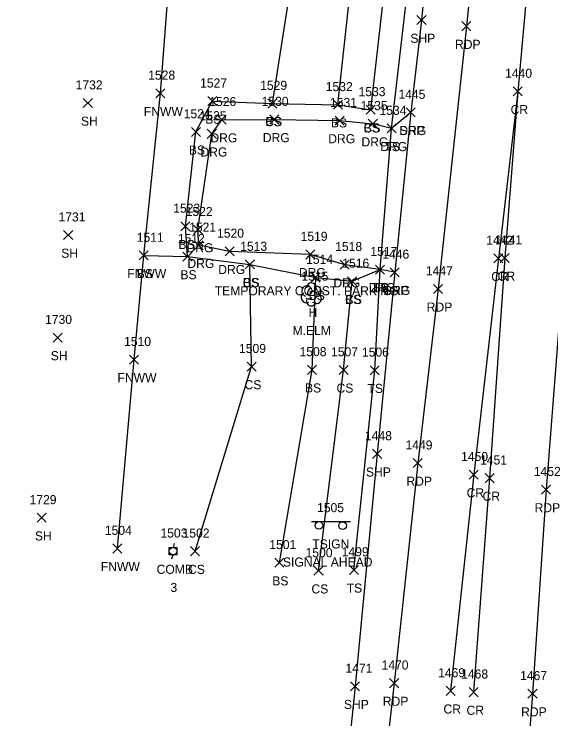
# Model space of a CAD drawing. Extents: x 1443960 to 1446865, y 610387 to 616706.
# Drawn here: x 1446473.8 to 1446592.3, y 610855.3 to 611010.8 of the extents above; entities that cross this region are included whole.
import ezdxf

# ---------------------------------------------------------------- set-up
doc = ezdxf.new("R2010")
doc.units = 0
for name, color, linetype in [('L_A', 7, 'Continuous'), ('L_C', 7, 'Continuous'), ('L_I', 7, 'Continuous'), ('L_TIC', 7, 'Continuous'), ('LELB', 7, 'Continuous'), ('LFNC', 7, 'Continuous'), ('LTD', 7, 'Continuous'), ('P_A', 7, 'Continuous'), ('P_I', 7, 'Continuous'), ('P_TIC', 7, 'Continuous'), ('PET', 7, 'Continuous'), ('PRC', 7, 'Continuous'), ('PSP', 7, 'Continuous'), ('R_A', 7, 'Continuous'), ('R_C', 7, 'Continuous'), ('R_I', 7, 'Continuous'), ('R_TIC', 7, 'Continuous'), ('RDG', 7, 'Continuous'), ('S_A', 7, 'Continuous'), ('S_C', 7, 'Continuous'), ('S_I', 7, 'Continuous'), ('SSGN', 7, 'Continuous'), ('U_A', 7, 'Continuous'), ('U_C', 7, 'Continuous'), ('U_I', 7, 'Continuous'), ('UP', 7, 'Continuous')]:
    doc.layers.add(name, color=color, linetype=linetype)

msp = doc.modelspace()

# ---------------------------------------------------------------- linework, layer by layer
at = {"layer": 'L_TIC'}
for points in [[(1446505.14, 610992.3), (1446507.14, 610994.3)], [(1446507.14, 610992.3), (1446505.14, 610994.3)], [(1446489.12, 610990.15), (1446491.12, 610992.15)], [(1446491.12, 610990.15), (1446489.12, 610992.15)], [(1446516.6, 610990.57), (1446518.6, 610992.57)], [(1446518.6, 610990.57), (1446516.6, 610992.57)], [(1446529.86, 610990.05), (1446531.86, 610992.05)], [(1446531.86, 610990.05), (1446529.86, 610992.05)], [(1446529.86, 610990.05), (1446531.86, 610992.05)], [(1446531.86, 610990.05), (1446529.86, 610992.05)], [(1446544.33, 610989.77), (1446546.33, 610991.77)], [(1446546.33, 610989.77), (1446544.33, 610991.77)], [(1446544.33, 610989.77), (1446546.33, 610991.77)], [(1446546.33, 610989.77), (1446544.33, 610991.77)], [(1446551.56, 610988.66), (1446553.56, 610990.66)], [(1446553.56, 610988.66), (1446551.56, 610990.66)], [(1446551.56, 610988.66), (1446553.56, 610990.66)], [(1446553.56, 610988.66), (1446551.56, 610990.66)], [(1446512.98, 610983.78), (1446514.98, 610985.78)], [(1446514.98, 610983.78), (1446512.98, 610985.78)], [(1446556.18, 610984.54), (1446558.18, 610986.54)], [(1446558.18, 610984.54), (1446556.18, 610986.54)], [(1446510.67, 610962.96), (1446512.67, 610964.96)], [(1446512.67, 610962.96), (1446510.67, 610964.96)], [(1446484.78, 610961.03), (1446486.78, 610963.03)], [(1446486.78, 610961.03), (1446484.78, 610963.03)], [(1446501.47, 610956.54), (1446503.47, 610958.54)], [(1446503.47, 610956.54), (1446501.47, 610958.54)], [(1446501.47, 610956.54), (1446503.47, 610958.54)], [(1446503.47, 610956.54), (1446501.47, 610958.54)], [(1446511.12, 610956.29), (1446513.12, 610958.29)], [(1446513.12, 610956.29), (1446511.12, 610958.29)], [(1446511.12, 610956.29), (1446513.12, 610958.29)], [(1446513.12, 610956.29), (1446511.12, 610958.29)], [(1446524.88, 610954.55), (1446526.88, 610956.55)], [(1446526.88, 610954.55), (1446524.88, 610956.55)], [(1446524.88, 610954.55), (1446526.88, 610956.55)], [(1446526.88, 610954.55), (1446524.88, 610956.55)], [(1446553.61, 610953.43), (1446555.61, 610955.43)], [(1446555.61, 610953.43), (1446553.61, 610955.43)], [(1446553.61, 610953.43), (1446555.61, 610955.43)], [(1446555.61, 610953.43), (1446553.61, 610955.43)], [(1446539.42, 610951.68), (1446541.42, 610953.68)], [(1446541.42, 610951.68), (1446539.42, 610953.68)], [(1446539.42, 610951.68), (1446541.42, 610953.68)], [(1446541.42, 610951.68), (1446539.42, 610953.68)], [(1446547.46, 610950.84), (1446549.46, 610952.84)], [(1446549.46, 610950.84), (1446547.46, 610952.84)], [(1446547.46, 610950.84), (1446549.46, 610952.84)], [(1446549.46, 610950.84), (1446547.46, 610952.84)], [(1446482.46, 610938.43), (1446484.46, 610940.43)], [(1446484.46, 610938.43), (1446482.46, 610940.43)], [(1446499.33, 610933.58), (1446501.33, 610935.58)], [(1446501.33, 610933.58), (1446499.33, 610935.58)], [(1446525.27, 610932.03), (1446527.27, 610934.03)], [(1446527.27, 610932.03), (1446525.27, 610934.03)], [(1446538.62, 610931.32), (1446540.62, 610933.32)], [(1446540.62, 610931.32), (1446538.62, 610933.32)], [(1446545.57, 610931.29), (1446547.57, 610933.29)], [(1446547.57, 610931.29), (1446545.57, 610933.29)], [(1446552.44, 610931.22), (1446554.44, 610933.22)], [(1446554.44, 610931.22), (1446552.44, 610933.22)], [(1446478.96, 610898.69), (1446480.96, 610900.69)], [(1446480.96, 610898.69), (1446478.96, 610900.69)], [(1446495.64, 610891.92), (1446497.64, 610893.92)], [(1446497.64, 610891.92), (1446495.64, 610893.92)], [(1446512.8, 610891.32), (1446514.8, 610893.32)], [(1446514.8, 610891.32), (1446512.8, 610893.32)], [(1446531.39, 610888.78), (1446533.39, 610890.78)], [(1446533.39, 610888.78), (1446531.39, 610890.78)], [(1446547.85, 610887.19), (1446549.85, 610889.19)], [(1446549.85, 610887.19), (1446547.85, 610889.19)], [(1446540.03, 610887), (1446542.03, 610889)], [(1446542.03, 610887), (1446540.03, 610889)]]:
    msp.add_lwpolyline(points, dxfattribs=at)
at = {"layer": 'LELB'}
for points in [[(1446548.85, 610888.19), (1446553.44, 610932.22), (1446554.61, 610954.43), (1446557.18, 610985.54), (1446561.83, 611026.07), (1446565.58, 611053.66), (1446570.69, 611096.92), (1446573.29, 611130.79), (1446568.51, 611145), (1446569.91, 611148.66), (1446564.88, 611156.7), (1446536.84, 611169.59), (1446508.69, 611183.48), (1446466.55, 611207.56), (1446427.27, 611227.8), (1446388.8, 611245), (1446349.69, 611268.25), (1446343.09, 611268.96)], [(1446545.33, 610990.77), (1446549.45, 611028.52), (1446549.03, 611055.59), (1446553.29, 611104.25), (1446542.01, 611115.66), (1446540.05, 611127.24), (1446544.04, 611129.96), (1446551.51, 611136.49), (1446553.27, 611138.91), (1446550.53, 611149.51), (1446533.12, 611159.93), (1446498.33, 611176.52), (1446468.4, 611193.46), (1446432.91, 611211.11), (1446396.49, 611230.29), (1446366.67, 611244.64), (1446348.43, 611256.48)], [(1446530.86, 610991.05), (1446536.61, 611027.8), (1446530.46, 611055.9), (1446528.01, 611097.29), (1446529.9, 611126.45), (1446531.13, 611139.44), (1446489.18, 611159.91), (1446465.02, 611182.42), (1446422.58, 611193.97), (1446390.63, 611222.09), (1446361.12, 611230.87), (1446345.74, 611242.49)], [(1446552.56, 610989.66), (1446556.82, 611027.38), (1446558.99, 611054.38), (1446562.05, 611102.47), (1446562.29, 611110), (1446552.62, 611117.46), (1446544.98, 611124.73), (1446545.64, 611126.22), (1446556.66, 611130.04), (1446565.54, 611129.7), (1446560.88, 611143.04), (1446563.36, 611147.94)], [(1446512.12, 610957.29), (1446511.67, 610963.96), (1446513.98, 610984.78), (1446517.6, 610991.57), (1446530.86, 610991.05), (1446545.33, 610990.77), (1446552.56, 610989.66)], [(1446502.47, 610957.54), (1446512.12, 610957.29), (1446525.88, 610955.55), (1446540.42, 610952.68), (1446548.46, 610951.84), (1446554.61, 610954.43)], [(1446513.8, 610892.32), (1446526.27, 610933.03), (1446525.88, 610955.55)], [(1446532.39, 610889.78), (1446539.62, 610932.32), (1446540.42, 610952.68)], [(1446541.03, 610888), (1446546.57, 610932.29), (1446548.46, 610951.84)]]:
    msp.add_lwpolyline(points, dxfattribs=at)
at = {"layer": 'LFNC'}
msp.add_lwpolyline([(1446496.64, 610892.92), (1446500.33, 610934.58), (1446502.47, 610957.54), (1446506.14, 610993.3), (1446509.27, 611033.76), (1446510.72, 611057.66), (1446494.01, 611076.45)], dxfattribs=at)
at = {"layer": 'LTD'}
msp.add_line((1446539.4, 610948.98), (1446539.4, 610948.98), dxfattribs=at)
msp.add_line((1446539.4, 610948.98), (1446539.4, 610948.98), dxfattribs=at)
msp.add_arc((1446539.45, 610950.42), 1.05, 335.5272, 180.9563, dxfattribs=at)
for centre, major_axis, ratio, start_param, end_param in [((1446538.61, 610949.65), (1.21, -0.51), 0.895232, 1.570796, 4.712389), ((1446539.19, 610949.44), (-0.208, -0.792), 0.645439, 3.141593, 6.283185), ((1446539.9, 610948.82), (-0.5, 0.667), 0.989748, 3.141593, 6.283185), ((1446540.44, 610949.57), (-1.14, -0.48), 0.949671, 1.570796, 4.712389), ((1446538.32, 610948.27), (0.58, -1.04), 0.959034, 3.141593, 6.283185), ((1446538.94, 610948.23), (-0.625, -0.083), 0.423636, 0, 3.141593), ((1446540.4, 610948.15), (-1.09, 0.79), 0.841452, 1.570796, 4.712389), ((1446539.4, 610947.48), (0.26, 1.06), 0.942809, 1.570796, 4.712389)]:
    msp.add_ellipse(centre, major_axis=major_axis, ratio=ratio, start_param=start_param, end_param=end_param, dxfattribs=at)
at = {"layer": 'P_TIC'}
for points in [[(1446562.76, 611008.43), (1446564.76, 611010.43)], [(1446564.76, 611008.43), (1446562.76, 611010.43)], [(1446572.67, 611007.09), (1446574.67, 611009.09)], [(1446574.67, 611007.09), (1446572.67, 611009.09)], [(1446584, 610992.71), (1446586, 610994.71)], [(1446586, 610992.71), (1446584, 610994.71)], [(1446584, 610992.71), (1446586, 610994.71)], [(1446586, 610992.71), (1446584, 610994.71)], [(1446560.38, 610988.08), (1446562.38, 610990.08)], [(1446562.38, 610988.08), (1446560.38, 610990.08)], [(1446579.73, 610955.9), (1446581.73, 610957.9)], [(1446581.73, 610955.9), (1446579.73, 610957.9)], [(1446581.14, 610955.99), (1446583.14, 610957.99)], [(1446583.14, 610955.99), (1446581.14, 610957.99)], [(1446556.86, 610952.83), (1446558.86, 610954.83)], [(1446558.86, 610952.83), (1446556.86, 610954.83)], [(1446566.43, 610949.16), (1446568.43, 610951.16)], [(1446568.43, 610949.16), (1446566.43, 610951.16)], [(1446552.98, 610912.79), (1446554.98, 610914.79)], [(1446554.98, 610912.79), (1446552.98, 610914.79)], [(1446561.94, 610910.75), (1446563.94, 610912.75)], [(1446563.94, 610910.75), (1446561.94, 610912.75)], [(1446574.28, 610908.2), (1446576.28, 610910.2)], [(1446576.28, 610908.2), (1446574.28, 610910.2)], [(1446577.81, 610907.43), (1446579.81, 610909.43)], [(1446579.81, 610907.43), (1446577.81, 610909.43)], [(1446590.25, 610904.91), (1446592.25, 610906.91)], [(1446592.25, 610904.91), (1446590.25, 610906.91)], [(1446548.11, 610861.52), (1446550.11, 610863.52)], [(1446550.11, 610861.52), (1446548.11, 610863.52)], [(1446556.73, 610862.22), (1446558.73, 610864.22)], [(1446558.73, 610862.22), (1446556.73, 610864.22)], [(1446569.19, 610860.52), (1446571.19, 610862.52)], [(1446571.19, 610860.52), (1446569.19, 610862.52)], [(1446574.26, 610860.24), (1446576.26, 610862.24)], [(1446576.26, 610860.24), (1446574.26, 610862.24)], [(1446587.27, 610859.89), (1446589.27, 610861.89)], [(1446589.27, 610859.89), (1446587.27, 610861.89)]]:
    msp.add_lwpolyline(points, dxfattribs=at)
at = {"layer": 'PET'}
for points in [[(1446586.96, 611148.93), (1446585.91, 611138.65), (1446581.07, 611085.82), (1446577.8, 611049), (1446573.67, 611008.09), (1446567.43, 610950.16), (1446562.94, 610911.75), (1446557.73, 610863.22), (1446550.26, 610797.89), (1446543.48, 610732.42), (1446535.83, 610665.01), (1446522.7, 610589.27)], [(1446610.71, 611136.75), (1446609.78, 611124.94), (1446606.08, 611083.4), (1446602.84, 611045.86), (1446594.91, 610952.22), (1446591.25, 610905.91), (1446588.27, 610860.89), (1446582.86, 610791.01), (1446578.03, 610732.6), (1446571.55, 610656.07), (1446565.6, 610584.23)]]:
    msp.add_lwpolyline(points, dxfattribs=at)
at = {"layer": 'PRC'}
for points in [[(1446598.39, 611142.94), (1446597.49, 611132.62), (1446593.4, 611084.97), (1446589.92, 611047.69), (1446585, 610993.71), (1446580.73, 610956.9), (1446575.28, 610909.2), (1446570.19, 610861.52)], [(1446585, 610993.71), (1446582.14, 610956.99), (1446578.81, 610908.43), (1446575.26, 610861.24)]]:
    msp.add_lwpolyline(points, dxfattribs=at)
at = {"layer": 'PSP'}
msp.add_lwpolyline([(1446576.92, 611154.08), (1446576.88, 611153.48), (1446576.38, 611146.03), (1446571.14, 611086.78), (1446567.69, 611049.79), (1446563.76, 611009.43), (1446561.38, 610989.08), (1446557.86, 610953.83), (1446553.98, 610913.79), (1446549.11, 610862.52), (1446542.65, 610799.79), (1446535.25, 610731.33), (1446527.9, 610668.85), (1446515.47, 610590.43)], dxfattribs=at)
at = {"layer": 'R_TIC'}
for points in [[(1446560.38, 610988.08), (1446562.38, 610990.08)], [(1446562.38, 610988.08), (1446560.38, 610990.08)], [(1446518.68, 610986.47), (1446520.68, 610988.47)], [(1446520.68, 610986.47), (1446518.68, 610988.47)], [(1446530.26, 610986.52), (1446532.26, 610988.52)], [(1446532.26, 610986.52), (1446530.26, 610988.52)], [(1446544.7, 610986.28), (1446546.7, 610988.28)], [(1446546.7, 610986.28), (1446544.7, 610988.28)], [(1446552.02, 610985.58), (1446554.02, 610987.58)], [(1446554.02, 610985.58), (1446552.02, 610987.58)], [(1446552.02, 610985.58), (1446554.02, 610987.58)], [(1446554.02, 610985.58), (1446552.02, 610987.58)], [(1446556.18, 610984.54), (1446558.18, 610986.54)], [(1446558.18, 610984.54), (1446556.18, 610986.54)], [(1446516.49, 610983.35), (1446518.49, 610985.35)], [(1446518.49, 610983.35), (1446516.49, 610985.35)], [(1446513.42, 610962.23), (1446515.42, 610964.23)], [(1446515.42, 610962.23), (1446513.42, 610964.23)], [(1446513.61, 610958.78), (1446515.61, 610960.78)], [(1446515.61, 610958.78), (1446513.61, 610960.78)], [(1446520.42, 610957.44), (1446522.42, 610959.44)], [(1446522.42, 610957.44), (1446520.42, 610959.44)], [(1446538.21, 610956.75), (1446540.21, 610958.75)], [(1446540.21, 610956.75), (1446538.21, 610958.75)], [(1446545.83, 610954.5), (1446547.83, 610956.5)], [(1446547.83, 610954.5), (1446545.83, 610956.5)], [(1446553.61, 610953.43), (1446555.61, 610955.43)], [(1446555.61, 610953.43), (1446553.61, 610955.43)], [(1446556.86, 610952.83), (1446558.86, 610954.83)], [(1446558.86, 610952.83), (1446556.86, 610954.83)]]:
    msp.add_lwpolyline(points, dxfattribs=at)
at = {"layer": 'RDG'}
for points in [[(1446561.38, 610989.08), (1446557.18, 610985.54), (1446553.02, 610986.58)], [(1446557.86, 610953.83), (1446554.61, 610954.43), (1446546.83, 610955.5), (1446539.21, 610957.75), (1446521.42, 610958.44), (1446514.61, 610959.78), (1446514.42, 610963.23), (1446517.49, 610984.35), (1446519.68, 610987.47), (1446531.26, 610987.52), (1446545.7, 610987.28), (1446553.02, 610986.58)]]:
    msp.add_lwpolyline(points, dxfattribs=at)
at = {"layer": 'SSGN'}
for p, q in [((1446539.47, 610898.85), (1446548.07, 610898.85)), ((1446543.49, 610897.95), (1446543.49, 610897.95))]:
    msp.add_line(p, q, dxfattribs=at)
for centre in [(1446541.13, 610898.02), (1446546.35, 610897.95)]:
    msp.add_circle(centre, 0.833, dxfattribs=at)
at = {"layer": 'UP'}
for p, q in [((1446509.17, 610893.99), (1446508.92, 610893.16)), ((1446508.08, 610891.49), (1446508.08, 610893.16)), ((1446508.08, 610893.16), (1446509.75, 610893.16)), ((1446508.92, 610892.33), (1446508.92, 610892.33)), ((1446509.75, 610893.16), (1446509.75, 610891.49)), ((1446509.75, 610891.49), (1446508.08, 610891.49)), ((1446508.67, 610890.66), (1446508.92, 610891.49))]:
    msp.add_line(p, q, dxfattribs=at)
msp.add_circle((1446508.92, 610892.33), 0.833, dxfattribs=at)

# ---------------------------------------------------------------- texts
at = {"layer": 'L_A'}
for s, p in [('FNWW', (1446502.48, 610988.3)), ('BS', (1446516.04, 610986.57)), ('SH', (1446488.61, 610986.15)), ('CS', (1446529.3, 610986.05)), ('BS', (1446529.3, 610986.05)), ('BS', (1446543.77, 610985.77)), ('BS', (1446543.77, 610985.77)), ('CS', (1446551, 610984.66)), ('BS', (1446551, 610984.66)), ('TS', (1446555.59, 610980.54)), ('BS', (1446512.42, 610979.78)), ('BS', (1446510.11, 610958.96)), ('SH', (1446484.26, 610957.03)), ('FNWW', (1446498.82, 610952.54)), ('BS', (1446500.91, 610952.54)), ('BS', (1446510.56, 610952.29)), ('BS', (1446510.56, 610952.29)), ('CS', (1446524.32, 610950.55)), ('BS', (1446524.32, 610950.55)), ('TS', (1446553.01, 610949.43)), ('BS', (1446553.05, 610949.43)), ('BS', (1446538.86, 610947.68)), ('BS', (1446538.86, 610947.68)), ('CS', (1446546.9, 610946.84)), ('BS', (1446546.9, 610946.84)), ('H', (1446538.83, 610943.98)), ('SH', (1446481.94, 610934.43)), ('FNWW', (1446496.67, 610929.58)), ('CS', (1446524.71, 610928.03)), ('BS', (1446538.06, 610927.32)), ('CS', (1446545.01, 610927.29)), ('TS', (1446551.85, 610927.22)), ('SH', (1446478.45, 610894.69)), ('FNWW', (1446492.99, 610887.92)), ('CS', (1446512.24, 610887.32)), ('BS', (1446530.83, 610884.78)), ('CS', (1446539.48, 610883)), ('TS', (1446547.26, 610883.19))]:
    msp.add_text(s, height=2, dxfattribs=at).set_placement(p)
at = {"layer": 'L_C'}
msp.add_text('M.ELM', height=2, dxfattribs=at).set_placement((1446535.3, 610939.98))
at = {"layer": 'L_I'}
for s, p in [('1528', (1446503.44, 610996.3)), ('1527', (1446514.9, 610994.57)), ('1732', (1446487.43, 610994.15)), ('1529', (1446528.16, 610994.05)), ('1529', (1446528.16, 610994.05)), ('1532', (1446542.64, 610993.77)), ('1532', (1446542.64, 610993.77)), ('1533', (1446549.87, 610992.66)), ('1533', (1446549.87, 610992.66)), ('1534', (1446554.49, 610988.54)), ('1524', (1446511.28, 610987.78)), ('1523', (1446508.97, 610966.96)), ('1731', (1446483.65, 610965.03)), ('1511', (1446500.92, 610960.54)), ('1511', (1446500.92, 610960.54)), ('1512', (1446509.99, 610960.29)), ('1512', (1446509.99, 610960.29)), ('1513', (1446523.75, 610958.55)), ('1513', (1446523.75, 610958.55)), ('1517', (1446552.48, 610957.43)), ('1517', (1446552.48, 610957.43)), ('1514', (1446538.3, 610955.68)), ('1514', (1446538.3, 610955.68)), ('1516', (1446546.28, 610954.84)), ('1516', (1446546.28, 610954.84)), ('1515', (1446537.27, 610951.98)), ('1730', (1446480.68, 610942.43)), ('1510', (1446498.12, 610937.58)), ('1509', (1446523.49, 610936.03)), ('1508', (1446536.85, 610935.32)), ('1507', (1446543.8, 610935.29)), ('1506', (1446550.62, 610935.22)), ('1729', (1446477.26, 610902.69)), ('1504', (1446493.87, 610895.92)), ('1502', (1446511.03, 610895.32)), ('1501', (1446530.18, 610892.78)), ('1500', (1446538.18, 610891)), ('1499', (1446546.15, 610891.19))]:
    msp.add_text(s, height=2, dxfattribs=at).set_placement(p)
at = {"layer": 'P_A'}
for s, p in [('SHP', (1446561.3, 611004.43)), ('RDP', (1446571.16, 611003.09)), ('CR', (1446583.43, 610988.71)), ('CR', (1446583.43, 610988.71)), ('SHP', (1446558.91, 610984.08)), ('CR', (1446579.16, 610951.9)), ('CR', (1446580.57, 610951.99)), ('SHP', (1446555.39, 610948.83)), ('RDP', (1446564.91, 610945.16)), ('SHP', (1446551.51, 610908.79)), ('RDP', (1446560.43, 610906.75)), ('CR', (1446573.72, 610904.2)), ('CR', (1446577.25, 610903.43)), ('RDP', (1446588.73, 610900.91)), ('RDP', (1446555.22, 610858.22)), ('SHP', (1446546.65, 610857.52)), ('CR', (1446568.62, 610856.52)), ('CR', (1446573.7, 610856.24)), ('RDP', (1446585.75, 610855.89))]:
    msp.add_text(s, height=2, dxfattribs=at).set_placement(p)
at = {"layer": 'P_I'}
for s, p in [('1440', (1446582.22, 610996.71)), ('1440', (1446582.22, 610996.71)), ('1445', (1446558.68, 610992.08)), ('1442', (1446578.04, 610959.9)), ('1441', (1446580.02, 610959.99)), ('1446', (1446555.11, 610956.83)), ('1447', (1446564.73, 610953.16)), ('1448', (1446551.29, 610916.79)), ('1449', (1446560.24, 610914.75)), ('1450', (1446572.51, 610912.2)), ('1451', (1446576.69, 610911.43)), ('1452', (1446588.55, 610908.91)), ('1471', (1446546.98, 610865.52)), ('1470', (1446554.95, 610866.22)), ('1469', (1446567.44, 610864.52)), ('1468', (1446572.52, 610864.24)), ('1467', (1446585.53, 610863.89))]:
    msp.add_text(s, height=2, dxfattribs=at).set_placement(p)
at = {"layer": 'R_A'}
for p in [(1446558.87, 610984.08), (1446517.17, 610982.47), (1446528.74, 610982.52), (1446543.18, 610982.28), (1446550.51, 610981.58), (1446550.51, 610981.58), (1446554.67, 610980.54), (1446514.97, 610979.35), (1446511.9, 610958.23), (1446512.1, 610954.78), (1446518.91, 610953.44), (1446536.7, 610952.75), (1446544.32, 610950.5), (1446552.09, 610949.43), (1446555.35, 610948.83)]:
    msp.add_text('DRG', height=2, dxfattribs=at).set_placement(p)
at = {"layer": 'R_C'}
msp.add_text('TEMPORARY CONST. PARKING', height=2, dxfattribs=at).set_placement((1446518.13, 610948.75))
at = {"layer": 'R_I'}
for s, p in [('1445', (1446558.68, 610992.08)), ('1526', (1446516.93, 610990.47)), ('1530', (1446528.48, 610990.52)), ('1531', (1446543.57, 610990.28)), ('1535', (1446550.33, 610989.58)), ('1535', (1446550.33, 610989.58)), ('1534', (1446554.49, 610988.54)), ('1525', (1446514.79, 610987.35)), ('1522', (1446511.72, 610966.23)), ('1521', (1446512.48, 610962.78)), ('1520', (1446518.64, 610961.44)), ('1519', (1446537.08, 610960.75)), ('1518', (1446544.71, 610958.5)), ('1517', (1446552.48, 610957.43)), ('1446', (1446555.11, 610956.83))]:
    msp.add_text(s, height=2, dxfattribs=at).set_placement(p)
at = {"layer": 'S_A'}
msp.add_text('TSIGN', height=2, dxfattribs=at).set_placement((1446539.67, 610892.93))
at = {"layer": 'S_C'}
msp.add_text('SIGNAL AHEAD', height=2, dxfattribs=at).set_placement((1446533.18, 610888.93))
at = {"layer": 'S_I'}
msp.add_text('1505', height=2, dxfattribs=at).set_placement((1446540.72, 610900.93))
at = {"layer": 'U_A'}
msp.add_text('COMB', height=2, dxfattribs=at).set_placement((1446505.3, 610887.33))
at = {"layer": 'U_C'}
msp.add_text('3', height=2, dxfattribs=at).set_placement((1446508.35, 610883.33))
at = {"layer": 'U_I'}
msp.add_text('1503', height=2, dxfattribs=at).set_placement((1446506.15, 610895.33))

doc.saveas('drawing.dxf')
